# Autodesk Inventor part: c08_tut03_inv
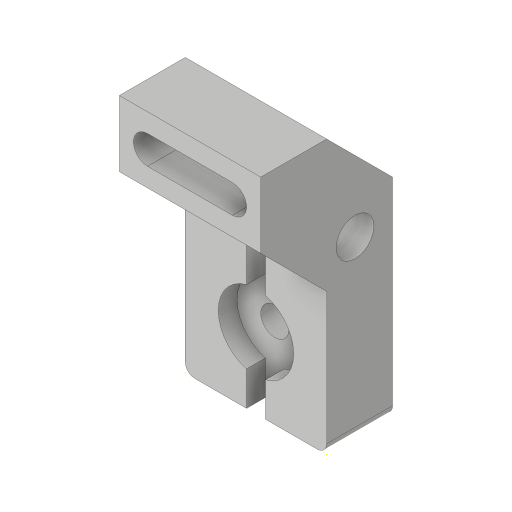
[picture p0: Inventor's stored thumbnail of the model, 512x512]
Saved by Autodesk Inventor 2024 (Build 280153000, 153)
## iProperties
Created: 2015-03
Part Number: c08_tut03_inv
Material: Generic
Document SubType Name: Modeling
Designer: Sandeep
Density: 1 g/cm^3
Appearance: Default
Author: Sandeep
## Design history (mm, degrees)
sketch "Sketch1"
  geometry: L1 (0, 0)-(0, 30); L2 (0, 30)-(-14, 44); L3 (-14, 44)-(-14, 58); L4 (-14, 58)-(0, 58); L5 (14, 44)-(14, 0); L6 (14, 0)-(0, 0); L7 (0, 58)-(14, 44)
  constraints: 14 end point, 3 parallel, 1 horizontal, 1 perpendicular, 1 vertical
  dimensions: "d0" = 14 distance between parallel lines of L5 L1; "d1" = 14 distance from line of L4.end L5; "d2" = 14 horizontal distance of L4.end L5.start; "d3" = 28 distance between parallel lines of L3 L5; "d4" = 58 distance between parallel lines of L4 L6; "d5" = 14 distance of L2.end L3.end
extrude "Extrusion1" new body sketch "Sketch1" distance "d6" = 30; taper "d7" = 0 deg
hole "Hole1" diameter "d10" = 8; stored, may be unused: countersink angle "d14" = 90 deg, drill point angle "d16" = 118 deg; dims "d8" = 21, "d9" = 8, "d11" = 6, "d12" = 4, "d13" = 2, "d15" = 8
sketch "Sketch3"
  geometry: L1 (0, 0)-(30, 0) reference; L2 (0, -30)-(30, -30) reference; L3 (30, 0)-(30, -30) reference; L4 (13, 0)-(13, -7.254); L5 (0, 3)-(30, 3) reference; L6 (17, 0)-(17, -7.254); L7 (15, -15)-(15, 7.075); L8 (13, 0)-(17, 0); L9 (-6.754, -15)-(33.848, -15); L10 (13, -22.746)-(13, -30); L11 (17, -30)-(17, -22.746); C1 r 3 at (15, -15); A1 r 8 centre (15, -15) between (13, -7.254) and (13, -22.746); A2 r 8 centre (15, -15) between (17, -22.746) and (17, -7.254)
  constraints: 14 end point, 5 point on line, 4 point on circle, 3 centre point, 2 parallel, 2 perpendicular, 1 coincident, 1 collinear, 1 horizontal, 1 vertical, 2 other
  dimensions: "d19" = 6 diameter of C1; "d21" = 15 distance from line of L2 A1.centre; "d22" = 15 distance from line of A1.centre L3; "d23" = 4 distance between parallel lines of L6 L4; "d24" = 4 distance between parallel lines of L11 L10; "d25" = 8 radius of A2; "d26" = 8 radius of A1
extrude "Extrusion2" cut sketch "Sketch3" distance "d27" = 4; taper "d28" = 0 deg
sketch "Sketch5"
  geometry: L1 (6, 7)-(24, 7); L2 (6, 4)-(24, 4); L3 (24, 10)-(6, 10); L4 (0, 14)-(30, 14) reference; L5 (30, 0)-(30, 14) reference; A1 r 3 centre (6, 7) between (6, 10) and (6, 4); A2 r 3 centre (24, 7) between (24, 4) and (24, 10); 2 further points
  constraints: 8 end point, 4 point on circle, 4 tangent, 2 centre point, 1 horizontal, 1 midpoint, 1 parallel
  dimensions: "d29" = 7 distance between parallel lines of L4 L1; "d30" = 18 distance of L1.start L1.end; "d31" = 6 distance from line of L5 L1.end; "d32" = 3 radius of A2
extrude "Extrusion3" cut sketch "Sketch5" distance "d33" = 11; taper "d34" = 0 deg
sketch "Sketch6"
  geometry: C1 r 3 at (0, 0); C2 r 3 at (0, 0) reference; 1 further point
  constraints: 1 centre point, 1 concentric
extrude "Extrusion4" cut sketch "Sketch6" distance "d35" = 35.25; taper "d36" = 0 deg
fillet "Fillet2" dims "d37" = 2
body "Solid1"
sketch "Sketch2"
  geometry: 1 further point
sketch "Sketch4"
  geometry: 1 further point
other parameters: "d20" = 16
